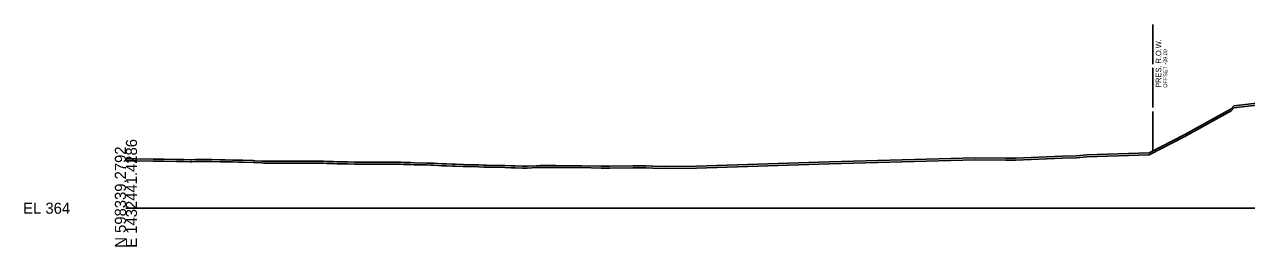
# Model space of a CAD drawing. Extents: x -26 to 2203, y -10 to 12201.
# Drawn here: x -25.7 to 283.7, y 4490.3 to 4546.4 of the extents above; entities that cross this region are included whole.
import ezdxf

# ---------------------------------------------------------------- set-up
doc = ezdxf.new("R2010")
doc.units = 0
for name, color, linetype in [('DESIGN - SHEET - Light Grid', 7, 'Continuous'), ('SURVEY - GROUND - Bottom of Topsoil Layer', 7, 'Continuous'), ('SURVEY - GROUND - Top of Ground', 7, 'Continuous'), ('SURVEY - PROPERTY - ROW Lines', 7, 'Continuous'), ('SURVEY - PROPERTY - ROW Lines Text', 7, 'Continuous')]:
    doc.layers.add(name, color=color, linetype=linetype)

msp = doc.modelspace()

# ---------------------------------------------------------------- linework, layer by layer
at = {"layer": 'DESIGN - SHEET - Light Grid'}
msp.add_line((0, 4500), (300, 4500), dxfattribs=at)
at = {"layer": 'SURVEY - GROUND - Bottom of Topsoil Layer'}
for p, q in [((268.13, 4518.13), (279.82, 4524.65)), ((279.82, 4524.65), (280.48, 4525.4)), ((280.48, 4525.4), (287.05, 4526.1)), ((259.09, 4513.48), (268.13, 4518.13)), ((0, 4511.97), (2.57, 4511.95)), ((2.57, 4511.95), (6.91, 4511.93)), ((6.91, 4511.93), (7.55, 4511.93)), ((7.55, 4511.93), (8.43, 4511.92)), ((8.43, 4511.92), (9.68, 4511.91)), ((9.68, 4511.91), (12.79, 4511.84)), ((12.79, 4511.84), (13.73, 4511.82)), ((13.73, 4511.82), (14.75, 4511.8)), ((14.75, 4511.8), (16.38, 4511.76)), ((16.38, 4511.76), (16.71, 4511.76)), ((16.71, 4511.76), (17.63, 4511.77)), ((17.63, 4511.77), (19.03, 4511.77)), ((19.03, 4511.77), (19.8, 4511.78)), ((19.8, 4511.78), (21.68, 4511.79)), ((21.68, 4511.79), (23.89, 4511.73)), ((23.89, 4511.73), (24.34, 4511.72)), ((24.34, 4511.72), (25.15, 4511.7)), ((25.15, 4511.7), (26.99, 4511.68)), ((26.99, 4511.68), (28.47, 4511.66)), ((28.47, 4511.66), (29.64, 4511.66)), ((29.64, 4511.66), (32.29, 4511.53)), ((32.29, 4511.53), (32.68, 4511.51)), ((178.04, 4511.24), (215.04, 4512.19)), ((215.04, 4512.19), (222.79, 4512.16)), ((222.79, 4512.16), (225.21, 4512.14)), ((225.21, 4512.14), (237.17, 4512.64)), ((237.17, 4512.64), (240.68, 4512.76)), ((240.68, 4512.76), (243.28, 4512.96)), ((243.28, 4512.96), (259.09, 4513.48)), ((32.68, 4511.51), (34.35, 4511.43)), ((34.35, 4511.43), (34.94, 4511.4)), ((34.94, 4511.4), (36.31, 4511.38)), ((36.31, 4511.38), (37.59, 4511.36)), ((37.59, 4511.36), (38.27, 4511.36)), ((38.27, 4511.36), (40.24, 4511.39)), ((40.24, 4511.39), (42.61, 4511.37)), ((42.61, 4511.37), (43.46, 4511.36)), ((43.46, 4511.36), (44.35, 4511.36)), ((44.35, 4511.36), (46.11, 4511.35)), ((46.11, 4511.35), (47.73, 4511.39)), ((47.73, 4511.39), (48.19, 4511.4)), ((48.19, 4511.4), (50.03, 4511.37)), ((50.03, 4511.37), (50.84, 4511.34)), ((50.84, 4511.34), (52.53, 4511.27)), ((52.53, 4511.27), (53.49, 4511.24)), ((53.49, 4511.24), (53.95, 4511.23)), ((53.95, 4511.23), (55.26, 4511.2)), ((55.26, 4511.2), (56.14, 4511.18)), ((56.14, 4511.18), (57.87, 4511.14)), ((57.87, 4511.14), (58.79, 4511.13)), ((58.79, 4511.13), (59.83, 4511.13)), ((59.83, 4511.13), (61.44, 4511.13)), ((61.44, 4511.13), (61.79, 4511.13)), ((61.79, 4511.13), (62.79, 4511.12)), ((62.79, 4511.12), (63.75, 4511.12)), ((63.75, 4511.12), (64.09, 4511.11)), ((64.09, 4511.11), (65.71, 4511.13)), ((65.71, 4511.13), (66.75, 4511.12)), ((66.75, 4511.12), (67.67, 4511.1)), ((67.67, 4511.1), (69.64, 4511.1)), ((69.64, 4511.1), (70.31, 4511.08)), ((70.31, 4511.08), (72.05, 4511.02)), ((72.05, 4511.02), (72.99, 4511)), ((72.99, 4511), (76.18, 4510.92)), ((76.18, 4510.92), (77.08, 4510.89)), ((77.08, 4510.89), (77.84, 4510.86)), ((77.84, 4510.86), (80, 4510.75)), ((80, 4510.75), (81.17, 4510.69)), ((81.17, 4510.69), (82.65, 4510.6)), ((82.65, 4510.6), (83.36, 4510.59)), ((83.36, 4510.59), (85.37, 4510.56)), ((85.37, 4510.56), (87.95, 4510.5)), ((87.95, 4510.5), (89.24, 4510.46)), ((89.24, 4510.46), (90.6, 4510.37)), ((90.6, 4510.37), (91.2, 4510.37)), ((91.2, 4510.37), (93.45, 4510.33)), ((93.45, 4510.33), (95.9, 4510.28)), ((95.9, 4510.28), (97.54, 4510.22)), ((97.54, 4510.22), (98.55, 4510.18)), ((98.55, 4510.18), (100.42, 4510.15)), ((100.42, 4510.15), (101.2, 4510.14)), ((101.2, 4510.14), (101.63, 4510.15)), ((101.63, 4510.15), (103.85, 4510.25)), ((103.85, 4510.25), (104.92, 4510.26)), ((104.92, 4510.26), (106.51, 4510.3)), ((106.51, 4510.3), (106.88, 4510.29)), ((106.88, 4510.29), (107.85, 4510.26)), ((107.85, 4510.26), (108.84, 4510.3)), ((108.84, 4510.3), (113.32, 4510.25)), ((113.32, 4510.25), (114.46, 4510.26)), ((114.46, 4510.26), (115.35, 4510.25)), ((115.35, 4510.25), (120.34, 4510.12)), ((120.34, 4510.12), (122.5, 4510.16)), ((122.5, 4510.16), (128.35, 4510.17)), ((128.35, 4510.17), (131.74, 4510.22)), ((131.74, 4510.22), (133.44, 4510.16)), ((133.44, 4510.16), (136.48, 4510.06)), ((136.48, 4510.06), (144.49, 4510.12)), ((144.49, 4510.12), (178.04, 4511.24))]:
    msp.add_line(p, q, dxfattribs=at)
at = {"layer": 'SURVEY - GROUND - Top of Ground'}
for p, q in [((268.13, 4518.63), (279.82, 4525.15)), ((279.82, 4525.15), (280.48, 4525.9)), ((280.48, 4525.9), (287.05, 4526.6)), ((259.09, 4513.98), (268.13, 4518.63)), ((0, 4512.47), (2.57, 4512.45)), ((2.57, 4512.45), (6.91, 4512.43)), ((6.91, 4512.43), (7.55, 4512.43)), ((7.55, 4512.43), (8.43, 4512.42)), ((8.43, 4512.42), (9.68, 4512.41)), ((9.68, 4512.41), (12.79, 4512.34)), ((12.79, 4512.34), (13.73, 4512.32)), ((13.73, 4512.32), (14.75, 4512.3)), ((14.75, 4512.3), (16.38, 4512.26)), ((16.38, 4512.26), (16.71, 4512.26)), ((16.71, 4512.26), (17.63, 4512.27)), ((17.63, 4512.27), (19.03, 4512.27)), ((19.03, 4512.27), (19.8, 4512.28)), ((19.8, 4512.28), (21.68, 4512.29)), ((21.68, 4512.29), (23.89, 4512.23)), ((23.89, 4512.23), (24.34, 4512.22)), ((24.34, 4512.22), (25.15, 4512.2)), ((25.15, 4512.2), (26.99, 4512.18)), ((26.99, 4512.18), (28.47, 4512.16)), ((28.47, 4512.16), (29.64, 4512.16)), ((29.64, 4512.16), (32.29, 4512.03)), ((32.29, 4512.03), (32.68, 4512.01)), ((32.68, 4512.01), (34.35, 4511.93)), ((34.35, 4511.93), (34.94, 4511.9)), ((34.94, 4511.9), (36.31, 4511.88)), ((36.31, 4511.88), (37.59, 4511.86)), ((37.59, 4511.86), (38.27, 4511.86)), ((38.27, 4511.86), (40.24, 4511.89)), ((40.24, 4511.89), (42.61, 4511.87)), ((42.61, 4511.87), (43.46, 4511.86)), ((43.46, 4511.86), (44.35, 4511.86)), ((44.35, 4511.86), (46.11, 4511.85)), ((46.11, 4511.85), (47.73, 4511.89)), ((47.73, 4511.89), (48.19, 4511.9)), ((48.19, 4511.9), (50.03, 4511.87)), ((50.03, 4511.87), (50.84, 4511.84)), ((50.84, 4511.84), (52.53, 4511.77)), ((52.53, 4511.77), (53.49, 4511.74)), ((53.49, 4511.74), (53.95, 4511.73)), ((53.95, 4511.73), (55.26, 4511.7)), ((55.26, 4511.7), (56.14, 4511.68)), ((56.14, 4511.68), (57.87, 4511.64)), ((57.87, 4511.64), (58.79, 4511.63)), ((58.79, 4511.63), (59.83, 4511.63)), ((59.83, 4511.63), (61.44, 4511.63)), ((61.44, 4511.63), (61.79, 4511.63)), ((61.79, 4511.63), (62.79, 4511.62)), ((62.79, 4511.62), (63.75, 4511.62)), ((63.75, 4511.62), (64.09, 4511.61)), ((64.09, 4511.61), (65.71, 4511.63)), ((65.71, 4511.63), (66.75, 4511.62)), ((66.75, 4511.62), (67.67, 4511.6)), ((67.67, 4511.6), (69.64, 4511.6)), ((69.64, 4511.6), (70.31, 4511.58)), ((70.31, 4511.58), (72.05, 4511.52)), ((72.05, 4511.52), (72.99, 4511.5)), ((144.49, 4510.62), (178.04, 4511.74)), ((178.04, 4511.74), (215.04, 4512.69)), ((215.04, 4512.69), (222.79, 4512.66)), ((222.79, 4512.66), (225.21, 4512.64)), ((225.21, 4512.64), (237.17, 4513.14)), ((237.17, 4513.14), (240.68, 4513.26)), ((240.68, 4513.26), (243.28, 4513.46)), ((243.28, 4513.46), (259.09, 4513.98)), ((72.99, 4511.5), (76.18, 4511.42)), ((76.18, 4511.42), (77.08, 4511.39)), ((77.08, 4511.39), (77.84, 4511.36)), ((77.84, 4511.36), (80, 4511.25)), ((80, 4511.25), (81.17, 4511.19)), ((81.17, 4511.19), (82.65, 4511.1)), ((82.65, 4511.1), (83.36, 4511.09)), ((83.36, 4511.09), (85.37, 4511.06)), ((85.37, 4511.06), (87.95, 4511)), ((87.95, 4511), (89.24, 4510.96)), ((89.24, 4510.96), (90.6, 4510.87)), ((90.6, 4510.87), (91.2, 4510.87)), ((91.2, 4510.87), (93.45, 4510.83)), ((93.45, 4510.83), (95.9, 4510.78)), ((95.9, 4510.78), (97.54, 4510.72)), ((97.54, 4510.72), (98.55, 4510.68)), ((98.55, 4510.68), (100.42, 4510.65)), ((100.42, 4510.65), (101.2, 4510.64)), ((101.2, 4510.64), (101.63, 4510.65)), ((101.63, 4510.65), (103.85, 4510.75)), ((103.85, 4510.75), (104.92, 4510.76)), ((104.92, 4510.76), (106.51, 4510.8)), ((106.51, 4510.8), (106.88, 4510.79)), ((106.88, 4510.79), (107.85, 4510.76)), ((107.85, 4510.76), (108.84, 4510.8)), ((108.84, 4510.8), (113.32, 4510.75)), ((113.32, 4510.75), (114.46, 4510.76)), ((114.46, 4510.76), (115.35, 4510.75)), ((115.35, 4510.75), (120.34, 4510.62)), ((120.34, 4510.62), (122.5, 4510.66)), ((122.5, 4510.66), (128.35, 4510.67)), ((128.35, 4510.67), (131.74, 4510.72)), ((131.74, 4510.72), (133.44, 4510.66)), ((133.44, 4510.66), (136.48, 4510.56)), ((136.48, 4510.56), (144.49, 4510.62))]:
    msp.add_line(p, q, dxfattribs=at)
at = {"layer": 'SURVEY - PROPERTY - ROW Lines'}
for p, q in [((260, 4536.45), (260, 4546.45)), ((260, 4525.45), (260, 4535.45)), ((260, 4514.45), (260, 4524.45))]:
    msp.add_line(p, q, dxfattribs=at)

# ---------------------------------------------------------------- texts
at = {"layer": 'DESIGN - SHEET - Light Grid'}
for s, p in [('N 598339.2792', (0, 4490)), ('E 1432441.4286', (2.8, 4490))]:
    msp.add_text(s, height=2.8, rotation=90, dxfattribs=at).set_placement(p)
msp.add_text('EL 364', height=2.8, dxfattribs=at).set_placement((-26, 4498.6))
at = {"layer": 'SURVEY - PROPERTY - ROW Lines Text'}
for s, height, p in [('PRES. R.O.W.', 1.4, (262.15, 4530.45)), ('OFFSET -39.00', 1, (263.65, 4530.45))]:
    msp.add_text(s, height=height, rotation=90, dxfattribs=at).set_placement(p)

doc.saveas('drawing.dxf')
